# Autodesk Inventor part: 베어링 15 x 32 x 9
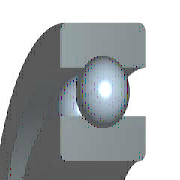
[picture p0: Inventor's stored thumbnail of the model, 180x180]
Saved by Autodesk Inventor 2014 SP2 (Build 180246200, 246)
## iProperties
IsCustomPart: 0
Created: 2012-02
Part Number: 베어링 15 x 32 x 9
Material: 강철, 연강
Description: 깊은 그루브 볼 베어링
Document SubType Name: Modeling
Standard: KS B 2023
Designer: mduedu
Standards Organization: KS
Language: ko-KR
Size Designation: 6002 - 15 x 32 x 9
Categories: <MemberInstance><Categories><Category DisplayName="샤프트 부품" InternalName="7f7aeb1f-a693-4053-b835-cee3144e0d98" Mnemonic="SHFT"><Category DisplayName="베어링" Inter
Density: 1 g/cm^3
Appearance: 노란색
Author: mduedu
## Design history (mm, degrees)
sketch "스케치" dims "d0" = 4.42 (= -0.26 x WD + 0.26 x BD)
  geometry: L1 (2.29, 11.75)-(6.71, 11.75); L2 (4.5, 11.75)-(4.5, 9.54); L3 (4.5, 11.75)-(4.5, 13.96); L4 (2.858, 10.271)-(0, 10.271); L5 (0, 7.5)-(9, 7.5); L6 (2.858, 13.229)-(0, 13.229); L7 (0, 16)-(9, 16); L8 (9, 7.5)-(9, 10.271); L9 (6.142, 10.271)-(9, 10.271); L10 (6.142, 13.229)-(9, 13.229); L11 (9, 16)-(9, 13.229); L12 (-1.4, 0)-(8.4, 0) reference; L13 (0, -0.3)-(0, 5.3) reference
  constraints: 22 end point, 4 point on line, 2 collinear, 2 perpendicular, 2 symmetric about line, 1 midpoint, 1 parallel, 14 other
  dimensions: "d9" = 15 diameter of L5 L12 (= WD); "d11" = 32 diameter of L7 L12 (= BD); "d12" = 9 distance between parallel lines of L8 L13 (= KB); "d13" = 20.542 diameter of L9 L12 (= 0.326 x BD + 0.674 x WD)
revolve "본체" stored, may be unused: angle "d6" = 90 deg
revolve "볼" stored, may be unused: angle "d7" = 90 deg
pattern_circular "IDS_ARRAYBALL[SIMPL:T]" dims angle "d3" = 360 deg
body "Solid1"
fillet "모깎기1" dims "d1" = 0.3 (= KRS)
other parameters: "WD" = 15 [user parameter; used in 5 equation terms], "BD" = 32 [user parameter; used in 5 equation terms], "KB" = 9 [user parameter; used in 1 equation term], "KRS" = 0.3 [user parameter; used in 1 equation term], "d4" = 0, "d5" = 0, "d8" = 0, "d14" = 0, "d15" = 0, "BBA" = 0 [user parameter], "BC0" = 2850000 [user parameter], "BC" = 5590000 [user parameter], "BR" = 16 (= 0.5 x BD) [user parameter], "WR" = 7.5 (= 0.5 x WD) [user parameter]
